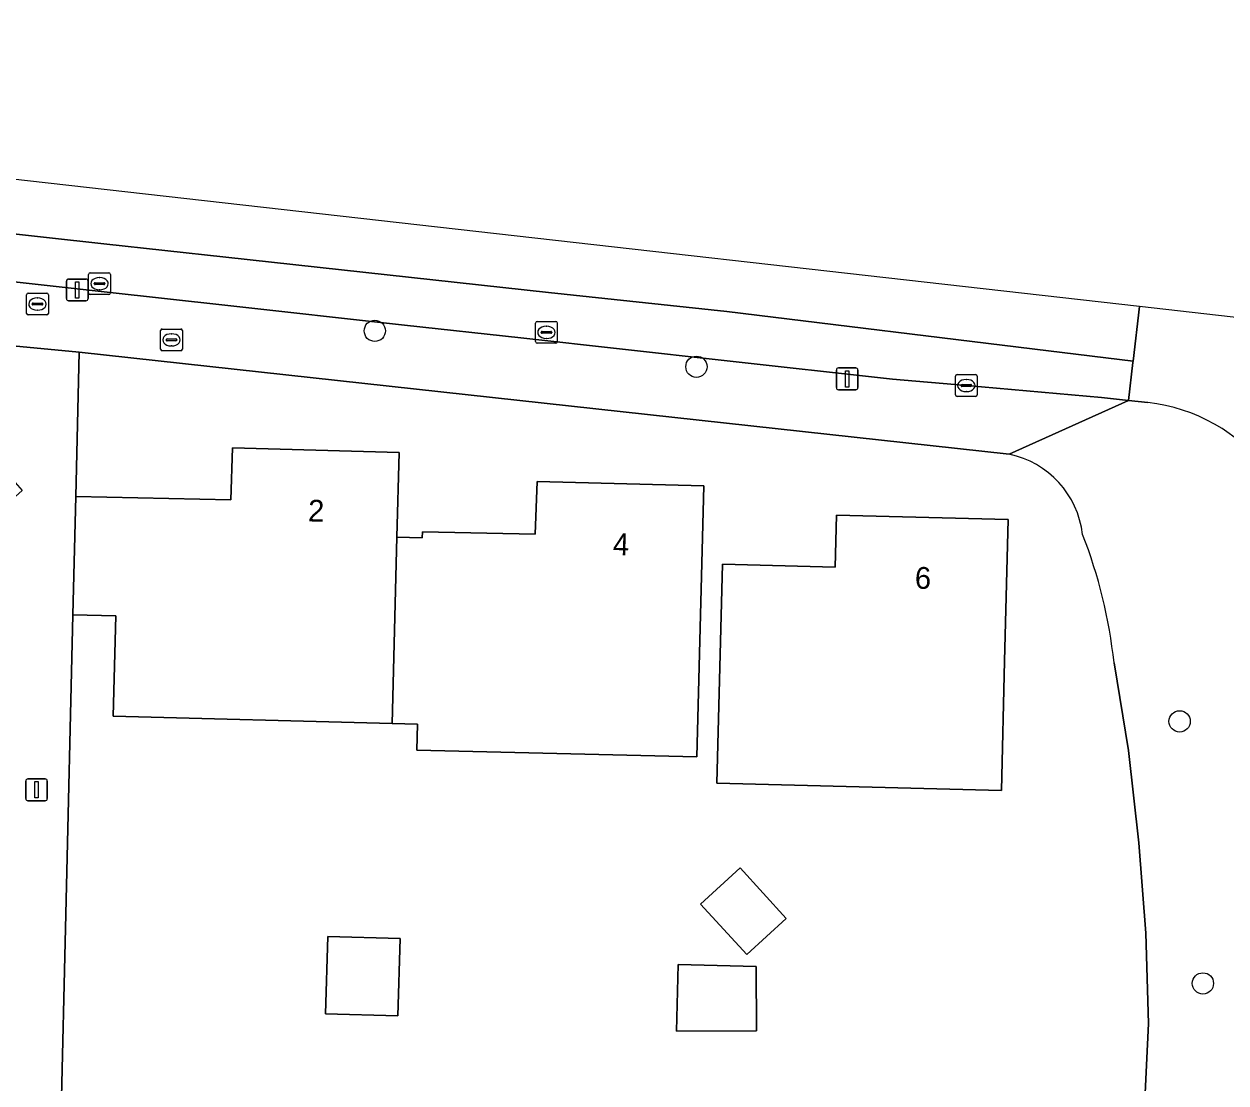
# Model space of a CAD drawing. Extents: x 162082 to 163401, y 388089 to 388636.
# Drawn here: x 162674.3 to 162729.5, y 388539 to 388587.6 of the extents above; entities that cross this region are included whole.
import ezdxf

# ---------------------------------------------------------------- set-up
doc = ezdxf.new("R2010")
doc.units = 0
for name, color, linetype in [('IMGEO_Boom', 7, 'Continuous'), ('IMGEO_Brandkraan', 7, 'Continuous'), ('IMGEO_Erf', 7, 'Continuous'), ('IMGEO_Kolk', 7, 'Continuous'), ('IMGEO_Lichtmast', 7, 'Continuous'), ('IMGEO_Muur', 7, 'Continuous'), ('IMGEO_Pand', 7, 'Continuous'), ('IMGEO_Pand_nummerreeks', 7, 'Continuous'), ('IMGEO_Rijbaan_lokaal_gesloten', 7, 'Continuous'), ('IMGEO_Rioolput', 7, 'Continuous'), ('IMGEO_Voetpad_open', 7, 'Continuous')]:
    doc.layers.add(name, color=color, linetype=linetype)

msp = doc.modelspace()

# ---------------------------------------------------------------- linework, layer by layer
at = {"layer": 'IMGEO_Boom'}
for centre in [(162690.391, 388573.475), (162705.152, 388571.825), (162727.328, 388555.546), (162728.395, 388543.518)]:
    msp.add_circle(centre, 0.489, dxfattribs=at)
at = {"layer": 'IMGEO_Brandkraan'}
for p, q in [((162680.558, 388572.633), (162680.558, 388573.485)), ((162680.633, 388573.559), (162681.485, 388573.559)), ((162681.046, 388573.339), (162681.071, 388573.339)), ((162681.559, 388573.485), (162681.559, 388572.633)), ((162680.817, 388573.053), (162680.817, 388573.065)), ((162681.255, 388573.016), (162680.857, 388573.016)), ((162680.86, 388573.102), (162681.258, 388573.102)), ((162681.069, 388572.779), (162681.044, 388572.779)), ((162681.301, 388573.065), (162681.301, 388573.053)), ((162681.485, 388572.559), (162680.633, 388572.559))]:
    msp.add_line(p, q, dxfattribs=at)
for points in [[(162680.558, 388572.633), (162680.558, 388573.485)], [(162680.633, 388573.559), (162681.485, 388573.559)], [(162681.559, 388573.485), (162681.559, 388572.633)], [(162681.485, 388572.559), (162680.633, 388572.559)]]:
    msp.add_lwpolyline(points, dxfattribs=at)
for centre, radius, start, end in [((162680.635, 388573.483), 0.0765, 91.552, 178.448), ((162680.635, 388573.483), 0.0765, 91.552, 178.448), ((162681.483, 388573.483), 0.0765, 1.552, 88.448), ((162681.483, 388573.483), 0.0765, 1.552, 88.448), ((162680.857, 388573.062), 0.0403, 85.8775, 175.7526), ((162680.854, 388573.052), 0.0366, 178.938, 274.7102), ((162681.258, 388573.059), 0.043, 264.8664, 352.4533), ((162681.262, 388573.064), 0.0386, 1.7309, 96.639), ((162680.635, 388572.635), 0.0765, 181.552, 268.448), ((162680.635, 388572.635), 0.0765, 181.552, 268.448), ((162681.483, 388572.635), 0.0765, 271.552, 358.448), ((162681.483, 388572.635), 0.0765, 271.552, 358.448)]:
    msp.add_arc(centre, radius, start, end, dxfattribs=at)
for centre, major_axis, ratio, start_param, end_param in [((162681.045, 388573.059), (-0.387, 0.002), 0.722429, 4.712389, 7.853982), ((162681.07, 388573.059), (-0.39, 0.002), 0.717154, 1.570796, 4.712389)]:
    msp.add_ellipse(centre, major_axis=major_axis, ratio=ratio, start_param=start_param, end_param=end_param, dxfattribs=at)
at = {"layer": 'IMGEO_Erf'}
for points in [[(162719.505, 388567.811), (162676.819, 388572.495), (162676.662, 388565.871), (162683.784, 388565.711), (162683.854, 388568.102), (162691.507, 388567.895), (162691.408, 388564.006), (162692.571, 388563.976), (162692.578, 388564.241), (162697.756, 388564.142), (162697.842, 388566.56), (162705.493, 388566.361), (162705.177, 388553.925), (162692.324, 388554.228), (162692.354, 388555.426), (162691.191, 388555.456), (162678.38, 388555.782), (162678.497, 388560.397), (162676.533, 388560.443), (162676.206, 388546.7), (162675.976, 388536.996), (162675.681, 388524.585)], [(162724.986, 388554.213), (162724.317, 388558.234)], [(162724.493, 388523.139), (162724.661, 388525.626), (162725.7, 388537.529), (162725.898, 388541.683), (162725.771, 388545.833), (162725.461, 388549.978), (162724.986, 388554.213)]]:
    msp.add_lwpolyline(points, dxfattribs=at)
for points in [[(162706.348, 388562.77), (162711.514, 388562.63), (162711.579, 388565.007), (162719.461, 388564.822), (162719.296, 388558.311), (162719.145, 388552.369), (162706.086, 388552.709)], [(162707.152, 388548.818), (162709.269, 388546.504), (162707.458, 388544.848), (162705.342, 388547.162)], [(162691.453, 388542.034), (162688.134, 388542.124), (162688.231, 388545.673), (162691.55, 388545.582)], [(162707.889, 388544.299), (162707.91, 388541.348), (162704.234, 388541.323), (162704.306, 388544.383)]]:
    msp.add_lwpolyline(points, close=True, dxfattribs=at)
for centre, radius, start, end in [((162718.634, 388563.635), 4.266, 6.6744, 78.2223), ((162701.738, 388555.823), 22.707, 6.0945, 21.4608)]:
    msp.add_arc(centre, radius, start, end, dxfattribs=at)
at = {"layer": 'IMGEO_Kolk'}
for p, q in [((162677.256, 388575.213), (162677.256, 388576.065)), ((162677.331, 388576.139), (162678.183, 388576.139)), ((162678.257, 388576.065), (162678.257, 388575.213)), ((162677.515, 388575.633), (162677.515, 388575.645)), ((162677.953, 388575.596), (162677.555, 388575.596)), ((162677.558, 388575.682), (162677.956, 388575.682)), ((162677.744, 388575.919), (162677.769, 388575.919)), ((162677.999, 388575.645), (162677.999, 388575.633)), ((162678.183, 388575.139), (162677.331, 388575.139)), ((162677.767, 388575.359), (162677.742, 388575.359)), ((162697.841, 388573.904), (162698.693, 388573.904)), ((162697.766, 388572.978), (162697.766, 388573.83)), ((162698.025, 388573.398), (162698.025, 388573.41)), ((162698.463, 388573.361), (162698.065, 388573.361)), ((162698.068, 388573.447), (162698.466, 388573.447)), ((162698.254, 388573.684), (162698.279, 388573.684)), ((162698.509, 388573.41), (162698.509, 388573.398)), ((162698.767, 388573.83), (162698.767, 388572.978)), ((162698.693, 388572.904), (162697.841, 388572.904)), ((162698.277, 388573.124), (162698.252, 388573.124)), ((162717.039, 388570.537), (162717.039, 388571.389)), ((162717.114, 388571.463), (162717.966, 388571.463)), ((162717.527, 388571.243), (162717.552, 388571.243)), ((162718.04, 388571.389), (162718.04, 388570.537)), ((162717.298, 388570.957), (162717.298, 388570.969)), ((162717.736, 388570.92), (162717.338, 388570.92)), ((162717.341, 388571.006), (162717.739, 388571.006)), ((162717.55, 388570.683), (162717.525, 388570.683)), ((162717.782, 388570.969), (162717.782, 388570.957)), ((162717.966, 388570.463), (162717.114, 388570.463))]:
    msp.add_line(p, q, dxfattribs=at)
for points in [[(162677.256, 388575.213), (162677.256, 388576.065)], [(162677.331, 388576.139), (162678.183, 388576.139)], [(162678.257, 388576.065), (162678.257, 388575.213)], [(162678.183, 388575.139), (162677.331, 388575.139)], [(162697.841, 388573.904), (162698.693, 388573.904)], [(162697.766, 388572.978), (162697.766, 388573.83)], [(162698.767, 388573.83), (162698.767, 388572.978)], [(162698.693, 388572.904), (162697.841, 388572.904)], [(162717.039, 388570.537), (162717.039, 388571.389)], [(162717.114, 388571.463), (162717.966, 388571.463)], [(162718.04, 388571.389), (162718.04, 388570.537)], [(162717.966, 388570.463), (162717.114, 388570.463)]]:
    msp.add_lwpolyline(points, dxfattribs=at)
for centre, radius, start, end in [((162677.333, 388576.063), 0.0765, 91.552, 178.448), ((162677.333, 388576.063), 0.0765, 91.552, 178.448), ((162678.181, 388576.063), 0.0765, 1.552, 88.448), ((162678.181, 388576.063), 0.0765, 1.552, 88.448), ((162677.555, 388575.642), 0.0403, 85.8775, 175.7526), ((162677.552, 388575.632), 0.0366, 178.938, 274.7102), ((162677.956, 388575.639), 0.043, 264.8664, 352.4533), ((162677.96, 388575.644), 0.0386, 1.7309, 96.639), ((162677.333, 388575.215), 0.0765, 181.552, 268.448), ((162677.333, 388575.215), 0.0765, 181.552, 268.448), ((162678.181, 388575.215), 0.0765, 271.552, 358.448), ((162678.181, 388575.215), 0.0765, 271.552, 358.448), ((162697.843, 388573.828), 0.0765, 91.552, 178.448), ((162697.843, 388573.828), 0.0765, 91.552, 178.448), ((162698.691, 388573.828), 0.0765, 1.552, 88.448), ((162698.691, 388573.828), 0.0765, 1.552, 88.448), ((162698.065, 388573.407), 0.0403, 85.8775, 175.7526), ((162698.062, 388573.397), 0.0366, 178.938, 274.7102), ((162698.466, 388573.404), 0.043, 264.8664, 352.4533), ((162698.47, 388573.409), 0.0386, 1.7309, 96.639), ((162697.843, 388572.98), 0.0765, 181.552, 268.448), ((162697.843, 388572.98), 0.0765, 181.552, 268.448), ((162698.691, 388572.98), 0.0765, 271.552, 358.448), ((162698.691, 388572.98), 0.0765, 271.552, 358.448), ((162717.116, 388571.387), 0.0765, 91.552, 178.448), ((162717.116, 388571.387), 0.0765, 91.552, 178.448), ((162717.964, 388571.387), 0.0765, 1.552, 88.448), ((162717.964, 388571.387), 0.0765, 1.552, 88.448), ((162717.338, 388570.966), 0.0403, 85.8775, 175.7526), ((162717.335, 388570.956), 0.0366, 178.938, 274.7102), ((162717.739, 388570.963), 0.043, 264.8664, 352.4533), ((162717.743, 388570.968), 0.0386, 1.7309, 96.639), ((162717.116, 388570.539), 0.0765, 181.552, 268.448), ((162717.116, 388570.539), 0.0765, 181.552, 268.448), ((162717.964, 388570.539), 0.0765, 271.552, 358.448), ((162717.964, 388570.539), 0.0765, 271.552, 358.448)]:
    msp.add_arc(centre, radius, start, end, dxfattribs=at)
for centre, major_axis, ratio, start_param, end_param in [((162677.743, 388575.639), (-0.387, 0.002), 0.722429, 4.712389, 7.853982), ((162677.768, 388575.639), (-0.39, 0.002), 0.717154, 1.570796, 4.712389), ((162698.253, 388573.404), (-0.387, 0.002), 0.722429, 4.712389, 7.853982), ((162698.278, 388573.404), (-0.39, 0.002), 0.717154, 1.570796, 4.712389), ((162717.526, 388570.963), (-0.387, 0.002), 0.722429, 4.712389, 7.853982), ((162717.551, 388570.963), (-0.39, 0.002), 0.717154, 1.570796, 4.712389)]:
    msp.add_ellipse(centre, major_axis=major_axis, ratio=ratio, start_param=start_param, end_param=end_param, dxfattribs=at)
at = {"layer": 'IMGEO_Lichtmast'}
for p, q in [((162676.239, 388574.954), (162676.239, 388575.754)), ((162676.239, 388575.754), (162676.239, 388574.954)), ((162676.339, 388575.854), (162677.129, 388575.854)), ((162677.129, 388575.854), (162676.339, 388575.854)), ((162677.229, 388575.754), (162677.229, 388574.954)), ((162677.229, 388574.954), (162677.229, 388575.754)), ((162677.129, 388574.854), (162676.339, 388574.854)), ((162676.339, 388574.854), (162677.129, 388574.854)), ((162711.572, 388570.87), (162711.572, 388571.67)), ((162711.572, 388571.67), (162711.572, 388570.87)), ((162711.672, 388571.77), (162712.462, 388571.77)), ((162712.462, 388571.77), (162711.672, 388571.77)), ((162712.562, 388571.67), (162712.562, 388570.87)), ((162712.562, 388570.87), (162712.562, 388571.67)), ((162712.462, 388570.77), (162711.672, 388570.77)), ((162711.672, 388570.77), (162712.462, 388570.77)), ((162674.47, 388552.906), (162675.26, 388552.906)), ((162675.26, 388552.906), (162674.47, 388552.906)), ((162674.37, 388552.006), (162674.37, 388552.806)), ((162674.37, 388552.806), (162674.37, 388552.006)), ((162675.36, 388552.806), (162675.36, 388552.006)), ((162675.36, 388552.006), (162675.36, 388552.806)), ((162675.26, 388551.906), (162674.47, 388551.906)), ((162674.47, 388551.906), (162675.26, 388551.906))]:
    msp.add_line(p, q, dxfattribs=at)
for points in [[(162676.659, 388575.729), (162676.809, 388575.729), (162676.809, 388574.979), (162676.659, 388574.979), (162676.659, 388575.729)], [(162711.992, 388571.645), (162712.142, 388571.645), (162712.142, 388570.895), (162711.992, 388570.895), (162711.992, 388571.645)], [(162674.79, 388552.781), (162674.94, 388552.781), (162674.94, 388552.031), (162674.79, 388552.031), (162674.79, 388552.781)]]:
    msp.add_lwpolyline(points, dxfattribs=at)
for centre, start, end in [((162676.339, 388575.754), 90, 180), ((162676.339, 388575.754), 90, 180), ((162677.129, 388575.754), 0, 90), ((162677.129, 388575.754), 360, 90), ((162676.339, 388574.954), 180, 270), ((162676.339, 388574.954), 180, 270), ((162677.129, 388574.954), 270, 0), ((162677.129, 388574.954), 270, 0), ((162711.672, 388571.67), 90, 180), ((162711.672, 388571.67), 90, 180), ((162712.462, 388571.67), 0, 90), ((162712.462, 388571.67), 360, 90), ((162711.672, 388570.87), 180, 270), ((162711.672, 388570.87), 180, 270), ((162712.462, 388570.87), 270, 0), ((162712.462, 388570.87), 270, 0), ((162674.47, 388552.806), 90, 180), ((162674.47, 388552.806), 90, 180), ((162675.26, 388552.806), 0, 90), ((162675.26, 388552.806), 360, 90), ((162674.47, 388552.006), 180, 270), ((162674.47, 388552.006), 180, 270), ((162675.26, 388552.006), 270, 0), ((162675.26, 388552.006), 270, 0)]:
    msp.add_arc(centre, 0.1, start, end, dxfattribs=at)
at = {"layer": 'IMGEO_Muur'}
for points in [[(162676.533, 388560.443), (162676.206, 388546.7)], [(162724.317, 388558.234), (162724.986, 388554.213), (162725.461, 388549.978), (162725.771, 388545.833), (162725.898, 388541.683), (162725.7, 388537.529), (162724.661, 388525.626)]]:
    msp.add_lwpolyline(points, dxfattribs=at)
at = {"layer": 'IMGEO_Pand'}
for points in [[(162691.408, 388564.006), (162691.507, 388567.895), (162683.854, 388568.102), (162683.784, 388565.711), (162676.662, 388565.871), (162676.533, 388560.443), (162678.497, 388560.397), (162678.38, 388555.782), (162691.191, 388555.456)], [(162705.493, 388566.361), (162697.842, 388566.56), (162697.756, 388564.142), (162692.578, 388564.241), (162692.571, 388563.976), (162691.408, 388564.006), (162691.191, 388555.456), (162692.354, 388555.426), (162692.324, 388554.228), (162705.177, 388553.925)], [(162719.296, 388558.311), (162719.461, 388564.822), (162711.579, 388565.007), (162711.514, 388562.63), (162706.348, 388562.77), (162706.086, 388552.709), (162719.145, 388552.369)], [(162705.342, 388547.162), (162707.458, 388544.848), (162709.269, 388546.504), (162707.152, 388548.818)], [(162688.134, 388542.124), (162691.453, 388542.034), (162691.55, 388545.582), (162688.231, 388545.673)], [(162704.234, 388541.323), (162707.91, 388541.348), (162707.889, 388544.299), (162704.306, 388544.383)]]:
    msp.add_lwpolyline(points, close=True, dxfattribs=at)
at = {"layer": 'IMGEO_Rijbaan_lokaal_gesloten'}
for points in [[(162725.483, 388574.587), (162648.58, 388583.286), (162648.309, 388580.74), (162677.949, 388577.463), (162683.559, 388576.851), (162698.362, 388575.236), (162706.548, 388574.359), (162721.311, 388572.557), (162725.188, 388572.084)], [(162698.362, 388575.236), (162683.559, 388576.851), (162677.949, 388577.463), (162648.309, 388580.74), (162648.076, 388578.584), (162678.104, 388575.254), (162683.5, 388574.656), (162691.747, 388573.741), (162697.09, 388573.149), (162706.422, 388572.114), (162714.151, 388571.264), (162717.54, 388570.963), (162723.74, 388570.414), (162724.976, 388570.284), (162725.18, 388572.019), (162725.188, 388572.084), (162721.311, 388572.557), (162706.548, 388574.359)]]:
    msp.add_lwpolyline(points, close=True, dxfattribs=at)
msp.add_lwpolyline([(162748.571, 388571.976), (162734.477, 388573.57), (162725.483, 388574.587), (162725.188, 388572.084), (162725.18, 388572.019), (162724.976, 388570.284), (162725.872, 388570.186)], dxfattribs=at)
msp.add_arc((162724.949, 388562.147), 8.091, 351.8048, 83.4516, dxfattribs=at)
at = {"layer": 'IMGEO_Rioolput'}
for p, q in [((162674.406, 388574.278), (162674.406, 388575.13)), ((162674.481, 388575.204), (162675.333, 388575.204)), ((162674.894, 388574.984), (162674.919, 388574.984)), ((162675.407, 388575.13), (162675.407, 388574.278)), ((162674.665, 388574.698), (162674.665, 388574.71)), ((162675.103, 388574.661), (162674.705, 388574.661)), ((162674.708, 388574.747), (162675.106, 388574.747)), ((162674.917, 388574.424), (162674.892, 388574.424)), ((162675.149, 388574.71), (162675.149, 388574.698)), ((162675.333, 388574.204), (162674.481, 388574.204))]:
    msp.add_line(p, q, dxfattribs=at)
for points in [[(162674.406, 388574.278), (162674.406, 388575.13)], [(162674.481, 388575.204), (162675.333, 388575.204)], [(162675.407, 388575.13), (162675.407, 388574.278)], [(162675.333, 388574.204), (162674.481, 388574.204)]]:
    msp.add_lwpolyline(points, dxfattribs=at)
for centre, radius, start, end in [((162674.483, 388575.128), 0.0765, 91.552, 178.448), ((162674.483, 388575.128), 0.0765, 91.552, 178.448), ((162675.331, 388575.128), 0.0765, 1.552, 88.448), ((162675.331, 388575.128), 0.0765, 1.552, 88.448), ((162674.705, 388574.707), 0.0403, 85.8775, 175.7526), ((162674.702, 388574.697), 0.0366, 178.938, 274.7102), ((162675.106, 388574.704), 0.043, 264.8664, 352.4533), ((162675.11, 388574.709), 0.0386, 1.7309, 96.639), ((162674.483, 388574.28), 0.0765, 181.552, 268.448), ((162674.483, 388574.28), 0.0765, 181.552, 268.448), ((162675.331, 388574.28), 0.0765, 271.552, 358.448), ((162675.331, 388574.28), 0.0765, 271.552, 358.448)]:
    msp.add_arc(centre, radius, start, end, dxfattribs=at)
for centre, major_axis, ratio, start_param, end_param in [((162674.893, 388574.704), (-0.387, 0.002), 0.722429, 4.712389, 7.853982), ((162674.918, 388574.704), (-0.39, 0.002), 0.717154, 1.570796, 4.712389)]:
    msp.add_ellipse(centre, major_axis=major_axis, ratio=ratio, start_param=start_param, end_param=end_param, dxfattribs=at)
at = {"layer": 'IMGEO_Voetpad_open'}
for points in [[(162534.972, 388586.774), (162539.096, 388587.558), (162539.844, 388587.475), (162543.513, 388587.071), (162545.123, 388586.893), (162580.248, 388583.173), (162637.605, 388576.802), (162673.783, 388572.792), (162676.819, 388572.495), (162719.505, 388567.811), (162724.976, 388570.284), (162723.74, 388570.414), (162717.54, 388570.963), (162714.151, 388571.264), (162706.422, 388572.114), (162697.09, 388573.149), (162691.747, 388573.741), (162683.5, 388574.656), (162678.104, 388575.254), (162648.076, 388578.584), (162642.099, 388579.246), (162626.892, 388580.933)], [(162725.872, 388570.186), (162724.976, 388570.284), (162719.505, 388567.811)], [(162724.317, 388558.234), (162724.986, 388554.213), (162725.461, 388549.978), (162725.771, 388545.833), (162725.898, 388541.683), (162725.7, 388537.529), (162724.661, 388525.626), (162724.493, 388523.139)]]:
    msp.add_lwpolyline(points, dxfattribs=at)
msp.add_lwpolyline([(162676.533, 388560.443), (162676.662, 388565.871), (162676.819, 388572.495), (162673.783, 388572.792), (162673.663, 388566.757), (162674.213, 388566.14), (162673.749, 388565.735), (162673.645, 388565.853), (162673.549, 388561.972), (162673.313, 388552.479), (162673.006, 388538.982), (162672.963, 388537.079), (162675.976, 388536.996), (162676.206, 388546.7)], close=True, dxfattribs=at)
for centre, radius, start, end in [((162724.949, 388562.147), 8.091, 351.8048, 83.4516), ((162718.634, 388563.635), 4.266, 6.6744, 78.2223), ((162701.738, 388555.823), 22.707, 6.0945, 21.4608)]:
    msp.add_arc(centre, radius, start, end, dxfattribs=at)

# ---------------------------------------------------------------- texts
at = {"layer": 'IMGEO_Pand_nummerreeks'}
for s, rotation, p in [('2', 358.453, (162687.314, 388564.728)), ('4', 358.5103, (162701.307, 388563.188)), ('6', 358.6554, (162715.168, 388561.642))]:
    msp.add_text(s, height=1, rotation=rotation, dxfattribs=at).set_placement(p)

doc.saveas('drawing.dxf')
